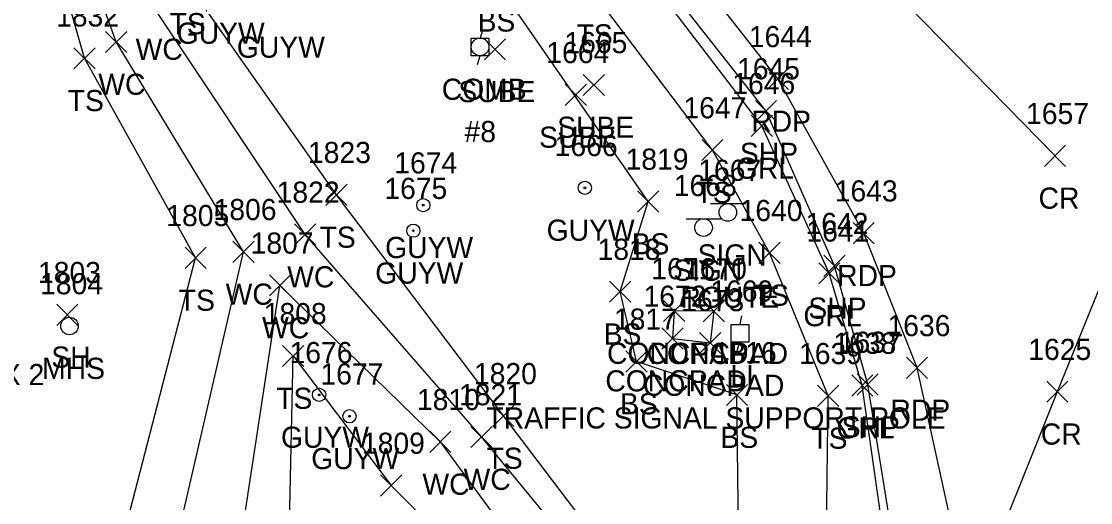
# Model space of a CAD drawing. Extents: x 1623612 to 1625808, y 621345 to 627748.
# Drawn here: x 1624593.7 to 1624694.8, y 626333.7 to 626379.2 of the extents above; entities that cross this region are included whole.
import ezdxf

# ---------------------------------------------------------------- set-up
doc = ezdxf.new("R2010")
doc.units = 0
for name, color, linetype in [('L_A', 7, 'Continuous'), ('L_I', 7, 'Continuous'), ('L_TIC', 7, 'Continuous'), ('LAWE', 7, 'Continuous'), ('LELB', 7, 'Continuous'), ('LS', 7, 'Continuous'), ('P_A', 7, 'Continuous'), ('P_I', 7, 'Continuous'), ('P_TIC', 7, 'Continuous'), ('PET', 7, 'Continuous'), ('PRC', 7, 'Continuous'), ('PSP', 7, 'Continuous'), ('R_A', 7, 'Continuous'), ('R_I', 7, 'Continuous'), ('R_TIC', 7, 'Continuous'), ('RGR', 7, 'Continuous'), ('S_A', 7, 'Continuous'), ('S_C', 7, 'Continuous'), ('S_I', 7, 'Continuous'), ('SSGN', 7, 'Continuous'), ('U_A', 7, 'Continuous'), ('U_C', 7, 'Continuous'), ('U_I', 7, 'Continuous'), ('U_TIC', 7, 'Continuous'), ('ULP', 7, 'Continuous'), ('UP', 7, 'Continuous'), ('UPGW', 7, 'Continuous'), ('USMH', 7, 'Continuous')]:
    doc.layers.add(name, color=color, linetype=linetype)

msp = doc.modelspace()

# ---------------------------------------------------------------- linework, layer by layer
at = {"layer": 'L_TIC'}
for points in [[(1624601.68, 626376.24), (1624603.68, 626378.24)], [(1624603.68, 626376.24), (1624601.68, 626378.24)], [(1624598.69, 626374.7), (1624600.69, 626376.7)], [(1624600.69, 626374.7), (1624598.69, 626376.7)], [(1624658.04, 626366.02), (1624660.04, 626368.02)], [(1624660.04, 626366.02), (1624658.04, 626368.02)], [(1624622.5, 626361.79), (1624624.5, 626363.79)], [(1624624.5, 626361.79), (1624622.5, 626363.79)], [(1624651.97, 626361.16), (1624653.97, 626363.16)], [(1624653.97, 626361.16), (1624651.97, 626363.16)], [(1624619.54, 626358.04), (1624621.54, 626360.04)], [(1624621.54, 626358.04), (1624619.54, 626360.04)], [(1624613.72, 626356.4), (1624615.72, 626358.4)], [(1624615.72, 626356.4), (1624613.72, 626358.4)], [(1624663.44, 626356.31), (1624665.44, 626358.31)], [(1624665.44, 626356.31), (1624663.44, 626358.31)], [(1624609.19, 626355.83), (1624611.19, 626357.83)], [(1624611.19, 626355.83), (1624609.19, 626357.83)], [(1624617.16, 626353.23), (1624619.16, 626355.23)], [(1624619.16, 626353.23), (1624617.16, 626355.23)], [(1624649.32, 626352.64), (1624651.32, 626354.64)], [(1624651.32, 626352.64), (1624649.32, 626354.64)], [(1624597.07, 626350.45), (1624599.07, 626352.45)], [(1624599.07, 626350.45), (1624597.07, 626352.45)], [(1624654.43, 626350.81), (1624656.43, 626352.81)], [(1624656.43, 626350.81), (1624654.43, 626352.81)], [(1624658.18, 626350.8), (1624660.18, 626352.8)], [(1624660.18, 626350.8), (1624658.18, 626352.8)], [(1624658.18, 626350.8), (1624660.18, 626352.8)], [(1624660.18, 626350.8), (1624658.18, 626352.8)], [(1624654.27, 626348.21), (1624656.27, 626350.21)], [(1624656.27, 626348.21), (1624654.27, 626350.21)], [(1624657.83, 626347.79), (1624659.83, 626349.79)], [(1624659.83, 626347.79), (1624657.83, 626349.79)], [(1624657.83, 626347.79), (1624659.83, 626349.79)], [(1624659.83, 626347.79), (1624657.83, 626349.79)], [(1624618.41, 626346.56), (1624620.41, 626348.56)], [(1624620.41, 626346.56), (1624618.41, 626348.56)], [(1624650.86, 626346.04), (1624652.86, 626348.04)], [(1624652.86, 626346.04), (1624650.86, 626348.04)], [(1624660.36, 626342.87), (1624662.36, 626344.87)], [(1624662.36, 626342.87), (1624660.36, 626344.87)], [(1624668.98, 626342.79), (1624670.98, 626344.79)], [(1624670.98, 626342.79), (1624668.98, 626344.79)], [(1624638.28, 626340.89), (1624640.28, 626342.89)], [(1624640.28, 626340.89), (1624638.28, 626342.89)], [(1624636.21, 626338.9), (1624638.21, 626340.9)], [(1624638.21, 626338.9), (1624636.21, 626340.9)], [(1624632.32, 626338.44), (1624634.32, 626340.44)], [(1624634.32, 626338.44), (1624632.32, 626340.44)], [(1624627.68, 626334.31), (1624629.68, 626336.31)], [(1624629.68, 626334.31), (1624627.68, 626336.31)]]:
    msp.add_lwpolyline(points, dxfattribs=at)
at = {"layer": 'LAWE'}
for points in [[(1624478.34, 625960.64), (1624502.51, 626006.49), (1624510.02, 626033.48), (1624538.01, 626022.07), (1624539, 626026.11), (1624515.37, 626039.01), (1624525.82, 626080.12), (1624541.49, 626122.12), (1624557.13, 626161.32), (1624574.3, 626199.4), (1624588.96, 626242.23), (1624604.56, 626282.04), (1624612.69, 626318.46), (1624618.16, 626354.23), (1624633.32, 626339.44), (1624651.01, 626315.35), (1624653.64, 626319.94), (1624637.21, 626339.9), (1624620.54, 626359.04), (1624606.22, 626380.55), (1624599.51, 626405.02), (1624601.1, 626417.17), (1624599.39, 626418.68), (1624597.72, 626417.92)], [(1624475.9, 625962), (1624495.4, 626010.74), (1624513.45, 626053.64), (1624523.83, 626080.72), (1624539.75, 626122.53), (1624554.03, 626163.77), (1624569.78, 626201.47), (1624586.16, 626244.06), (1624600.64, 626283.77), (1624605.98, 626319.56), (1624614.72, 626357.4), (1624602.68, 626377.24), (1624598.91, 626387.68), (1624595.49, 626400.19), (1624596.27, 626415.38)]]:
    msp.add_lwpolyline(points, dxfattribs=at)
at = {"layer": 'LELB'}
for points in [[(1624669.8, 626328.28), (1624669.98, 626343.79), (1624664.44, 626357.31), (1624659.04, 626367.02), (1624647.79, 626381.91), (1624630.66, 626395.22), (1624597.45, 626435.36), (1624575.8, 626460.21), (1624547.36, 626492.23), (1624525.96, 626513.7), (1624497.97, 626546.1), (1624463.72, 626581.44), (1624438.46, 626609.8)], [(1624405.5, 625728.14), (1624428.24, 625773.19), (1624451.7, 625813.41), (1624479.3, 625869.39), (1624496.23, 625906.08), (1624514.91, 625948.11), (1624536.21, 625990.48), (1624546.45, 626029.66), (1624561.04, 626063.21), (1624576.65, 626110.9), (1624590.48, 626147.32), (1624609.26, 626181.73), (1624628.06, 626219.01), (1624648.51, 626267.43), (1624661.85, 626303.08), (1624661.36, 626343.87), (1624651.86, 626347.04), (1624650.32, 626353.64), (1624652.97, 626362.16), (1624638.4, 626383.22), (1624618.17, 626397.94), (1624604.09, 626415.44)], [(1624658.53, 626316.55), (1624639.28, 626341.89), (1624623.5, 626362.79), (1624609.32, 626382.97), (1624602.55, 626406.54), (1624604.09, 626415.44)], [(1624375.32, 625803.31), (1624399.86, 625843.95), (1624436.39, 625893.65), (1624461.77, 625932.24), (1624474.24, 625964.36), (1624492.43, 626012.44), (1624506.84, 626058.35), (1624517.83, 626084.66), (1624533.25, 626127.2), (1624547.8, 626166.97), (1624564.84, 626204.52), (1624581.23, 626246.76), (1624598.57, 626285.31), (1624600.66, 626320.03), (1624610.19, 626356.83), (1624599.69, 626375.7), (1624596.69, 626386.19), (1624590.38, 626400.67)], [(1624618.75, 626317.35), (1624619.41, 626347.56), (1624628.68, 626335.31), (1624655.24, 626308.57)]]:
    msp.add_lwpolyline(points, dxfattribs=at)
at = {"layer": 'LS'}
for points in [[(1624659.18, 626351.8), (1624655.43, 626351.81), (1624655.27, 626349.21), (1624658.83, 626348.79)], [(1624659.18, 626351.8), (1624658.83, 626348.79)]]:
    msp.add_lwpolyline(points, dxfattribs=at)
at = {"layer": 'P_TIC'}
for points in [[(1624664.22, 626372.75), (1624666.22, 626374.75)], [(1624666.22, 626372.75), (1624664.22, 626374.75)], [(1624663.11, 626369.71), (1624665.11, 626371.71)], [(1624665.11, 626369.71), (1624663.11, 626371.71)], [(1624690.43, 626365.48), (1624692.43, 626367.48)], [(1624692.43, 626365.48), (1624690.43, 626367.48)], [(1624672.34, 626358.16), (1624674.34, 626360.16)], [(1624674.34, 626358.16), (1624672.34, 626360.16)], [(1624669.58, 626355.08), (1624671.58, 626357.08)], [(1624671.58, 626355.08), (1624669.58, 626357.08)], [(1624677.38, 626345.43), (1624679.38, 626347.43)], [(1624679.38, 626345.43), (1624677.38, 626347.43)], [(1624672.72, 626343.86), (1624674.72, 626345.86)], [(1624674.72, 626343.86), (1624672.72, 626345.86)], [(1624690.64, 626343.18), (1624692.64, 626345.18)], [(1624692.64, 626343.18), (1624690.64, 626345.18)]]:
    msp.add_lwpolyline(points, dxfattribs=at)
at = {"layer": 'PET'}
msp.add_lwpolyline([(1624682.54, 626327.48), (1624678.38, 626346.43), (1624673.34, 626359.16), (1624665.22, 626373.75), (1624654.29, 626387.74), (1624639.33, 626403.95), (1624606.52, 626439.12), (1624581.34, 626466.22), (1624553.07, 626496.91), (1624531.24, 626520.29), (1624503.05, 626550.6), (1624469.83, 626586.28), (1624436.59, 626622.29), (1624410.08, 626650.63), (1624383.72, 626678.98), (1624351.7, 626713.55), (1624321.29, 626745.92), (1624294.74, 626773.91), (1624265.91, 626805.6)], dxfattribs=at)
at = {"layer": 'PRC'}
for points in [[(1624691.43, 626366.48), (1624669.78, 626388.58), (1624647.94, 626412.24), (1624616.12, 626446.54), (1624589.59, 626475.6), (1624562.81, 626504.24), (1624540.57, 626528.3), (1624511.37, 626559.76), (1624478.76, 626595.67), (1624444.94, 626631.16), (1624418.89, 626658.65), (1624393.01, 626686.5), (1624360.17, 626722.63), (1624331.53, 626753.24), (1624304.47, 626782.71), (1624275.06, 626813.9), (1624246.4, 626843.61), (1624219.02, 626871.9), (1624198.62, 626894.75), (1624176.28, 626917.84)], [(1624715.94, 626400.49), (1624704.96, 626376.94), (1624691.64, 626344.18), (1624683.71, 626324.4)]]:
    msp.add_lwpolyline(points, dxfattribs=at)
at = {"layer": 'PSP'}
msp.add_lwpolyline([(1624676.55, 626327.48), (1624673.72, 626344.86), (1624670.58, 626356.08), (1624664.11, 626370.71), (1624652.39, 626385.59), (1624636.52, 626401.6), (1624603.46, 626436.72), (1624579, 626463.66), (1624550.01, 626494.21), (1624528.45, 626517.8), (1624500.38, 626548.3), (1624466.85, 626583.85), (1624433.64, 626619.4), (1624408.06, 626646.48), (1624380.64, 626676.32), (1624349.24, 626711.12), (1624317.97, 626743.62), (1624292.14, 626770.88), (1624262.1, 626803.32)], dxfattribs=at)
at = {"layer": 'R_TIC'}
for points in [[(1624662.71, 626368.31), (1624664.71, 626370.31)], [(1624664.71, 626368.31), (1624662.71, 626370.31)], [(1624669.09, 626354.37), (1624671.09, 626356.37)], [(1624671.09, 626354.37), (1624669.09, 626356.37)], [(1624672.21, 626343.76), (1624674.21, 626345.76)], [(1624674.21, 626343.76), (1624672.21, 626345.76)]]:
    msp.add_lwpolyline(points, dxfattribs=at)
at = {"layer": 'RGR'}
msp.add_lwpolyline([(1624571, 626060.25), (1624575.84, 626063.1), (1624580.53, 626069.08), (1624596.69, 626108.34), (1624613, 626148.3), (1624628.7, 626186.79), (1624643.47, 626223.61), (1624657.22, 626257.17), (1624667.59, 626283.36), (1624674.43, 626306.16), (1624675.65, 626327.64), (1624673.21, 626344.76), (1624670.09, 626355.37), (1624663.71, 626369.31), (1624651.72, 626385.04), (1624634.25, 626398.65)], dxfattribs=at)
at = {"layer": 'SSGN'}
for p, q in [((1624658.86, 626361.97), (1624662.19, 626361.97)), ((1624660.5, 626361.13), (1624660.5, 626361.13)), ((1624656.55, 626360.52), (1624659.88, 626360.52)), ((1624658.2, 626359.69), (1624658.2, 626359.69))]:
    msp.add_line(p, q, dxfattribs=at)
for centre in [(1624660.5, 626361.13), (1624658.2, 626359.69)]:
    msp.add_circle(centre, 0.833, dxfattribs=at)
at = {"layer": 'U_TIC'}
for points in [[(1624637.49, 626375.55), (1624639.49, 626377.55)], [(1624639.49, 626375.55), (1624637.49, 626377.55)], [(1624646.83, 626372.18), (1624648.83, 626374.18)], [(1624648.83, 626372.18), (1624646.83, 626374.18)], [(1624645.13, 626371.24), (1624647.13, 626373.24)], [(1624647.13, 626371.24), (1624645.13, 626373.24)]]:
    msp.add_lwpolyline(points, dxfattribs=at)
at = {"layer": 'ULP'}
for p, q in [((1624661.8, 626351.36), (1624661.63, 626350.53)), ((1624660.8, 626348.86), (1624660.8, 626350.53)), ((1624660.8, 626350.53), (1624662.47, 626350.53)), ((1624662.47, 626350.53), (1624662.47, 626348.86)), ((1624662.47, 626348.86), (1624660.8, 626348.86)), ((1624661.38, 626348.03), (1624661.63, 626348.86)), ((1624661.63, 626349.7), (1624661.63, 626349.7))]:
    msp.add_line(p, q, dxfattribs=at)
at = {"layer": 'UP'}
for p, q in [((1624637.33, 626378.43), (1624637.08, 626377.6)), ((1624636.24, 626375.93), (1624636.24, 626377.6)), ((1624636.24, 626377.6), (1624637.91, 626377.6)), ((1624637.91, 626377.6), (1624637.91, 626375.93)), ((1624637.08, 626376.77), (1624637.08, 626376.77)), ((1624637.91, 626375.93), (1624636.24, 626375.93)), ((1624636.83, 626375.1), (1624637.08, 626375.93))]:
    msp.add_line(p, q, dxfattribs=at)
msp.add_circle((1624637.08, 626376.77), 0.833, dxfattribs=at)
at = {"layer": 'UPGW'}
for centre, radius in [((1624646.98, 626363.45), 0.625), ((1624646.98, 626363.45), 0.0833), ((1624631.71, 626361.81), 0.625), ((1624631.71, 626361.81), 0.0833), ((1624630.77, 626359.4), 0.625), ((1624630.77, 626359.4), 0.0833), ((1624621.86, 626343.88), 0.625), ((1624621.86, 626343.88), 0.0833), ((1624624.73, 626341.86), 0.625), ((1624624.73, 626341.86), 0.0833)]:
    msp.add_circle(centre, radius, dxfattribs=at)
at = {"layer": 'USMH'}
for p, q in [((1624598.27, 626350.39), (1624598.27, 626350.39)), ((1624599.1, 626350.39), (1624599.1, 626350.39))]:
    msp.add_line(p, q, dxfattribs=at)
msp.add_circle((1624598.27, 626350.39), 0.833, dxfattribs=at)

# ---------------------------------------------------------------- texts
at = {"layer": 'L_A'}
for s, p in [('BS', (1624636.84, 626378.22)), ('TS', (1624607.73, 626377.97)), ('TS', (1624646.2, 626376.91)), ('WC', (1624604.52, 626375.55)), ('WC', (1624600.99, 626372.24)), ('TS', (1624598.1, 626370.7)), ('TS', (1624657.45, 626362.02)), ('TS', (1624621.91, 626357.79)), ('BS', (1624651.41, 626357.16)), ('WC', (1624618.85, 626354.04)), ('TS', (1624608.6, 626351.83)), ('WC', (1624613.03, 626352.4)), ('TS', (1624662.85, 626352.31)), ('WC', (1624616.47, 626349.23)), ('BS', (1624648.76, 626348.64)), ('CONCPAD', (1624649.08, 626346.81)), ('CONCPAD', (1624652.82, 626346.8)), ('CONCPAD', (1624652.82, 626346.8)), ('SH', (1624596.55, 626346.45)), ('CONCPAD', (1624648.92, 626344.21)), ('CONCPAD', (1624652.47, 626343.79)), ('CONCPAD', (1624652.47, 626343.79)), ('TS', (1624617.81, 626342.56)), ('BS', (1624650.3, 626342.04)), ('BS', (1624659.8, 626338.87)), ('TS', (1624668.39, 626338.79)), ('TS', (1624637.69, 626336.89)), ('WC', (1624635.52, 626334.9)), ('WC', (1624631.63, 626334.44))]:
    msp.add_text(s, height=2, dxfattribs=at).set_placement(p)
at = {"layer": 'L_I'}
for s, p in [('1832', (1624597, 626378.7)), ('1647', (1624656.3, 626370.02)), ('1823', (1624620.81, 626365.79)), ('1819', (1624650.83, 626365.16)), ('1822', (1624617.85, 626362.04)), ('1806', (1624611.89, 626360.4)), ('1640', (1624661.61, 626360.31)), ('1805', (1624607.42, 626359.83)), ('1807', (1624615.39, 626357.23)), ('1818', (1624648.19, 626356.64)), ('1803', (1624595.29, 626354.45)), ('1671', (1624653.26, 626354.81)), ('1670', (1624656.35, 626354.8)), ('1670', (1624656.35, 626354.8)), ('1672', (1624652.53, 626352.21)), ('1673', (1624656.09, 626351.79)), ('1673', (1624656.09, 626351.79)), ('1808', (1624616.63, 626350.56)), ('1817', (1624649.73, 626350.04)), ('1816', (1624659.17, 626346.87)), ('1639', (1624667.23, 626346.79)), ('1820', (1624636.5, 626344.89)), ('1821', (1624635.09, 626342.9)), ('1810', (1624631.11, 626342.44)), ('1809', (1624625.91, 626338.31))]:
    msp.add_text(s, height=2, dxfattribs=at).set_placement(p)
at = {"layer": 'P_A'}
for s, p in [('RDP', (1624662.71, 626368.75)), ('SHP', (1624661.64, 626365.71)), ('CR', (1624689.87, 626361.48)), ('RDP', (1624670.83, 626354.16)), ('SHP', (1624668.11, 626351.08)), ('RDP', (1624675.87, 626341.43)), ('SHP', (1624671.26, 626339.86)), ('CR', (1624690.08, 626339.18))]:
    msp.add_text(s, height=2, dxfattribs=at).set_placement(p)
at = {"layer": 'P_I'}
for s, p in [('1644', (1624662.48, 626376.75)), ('1645', (1624661.37, 626373.71)), ('1657', (1624688.69, 626369.48)), ('1643', (1624670.6, 626362.16)), ('1642', (1624667.84, 626359.08)), ('1636', (1624675.59, 626349.43)), ('1637', (1624670.98, 626347.86)), ('1625', (1624688.9, 626347.18))]:
    msp.add_text(s, height=2, dxfattribs=at).set_placement(p)
at = {"layer": 'R_A'}
for p in [(1624661.26, 626364.31), (1624667.64, 626350.37), (1624670.76, 626339.76)]:
    msp.add_text('GRL', height=2, dxfattribs=at).set_placement(p)
at = {"layer": 'R_I'}
for s, p in [('1646', (1624660.92, 626372.31)), ('1641', (1624667.92, 626358.37)), ('1638', (1624670.47, 626347.76))]:
    msp.add_text(s, height=2, dxfattribs=at).set_placement(p)
at = {"layer": 'S_A'}
for p in [(1624657.64, 626356.11), (1624655.33, 626354.67)]:
    msp.add_text('SIGN', height=2, dxfattribs=at).set_placement(p)
at = {"layer": 'S_C'}
msp.add_text('ROUTE', height=2, dxfattribs=at).set_placement((1624656.01, 626352.11))
at = {"layer": 'S_I'}
for s, p in [('1667', (1624657.7, 626364.11)), ('1668', (1624655.39, 626362.67))]:
    msp.add_text(s, height=2, dxfattribs=at).set_placement(p)
at = {"layer": 'U_A'}
for s, p in [('GUYW', (1624608.4, 626377.07)), ('GUYW', (1624614.09, 626375.75)), ('COMB', (1624633.46, 626371.77)), ('SUBE', (1624635.02, 626371.55)), ('SUBE', (1624644.37, 626368.18)), ('SUBE', (1624642.66, 626367.24)), ('GUYW', (1624643.37, 626358.45)), ('GUYW', (1624628.1, 626356.81)), ('GUYW', (1624627.17, 626354.4)), ('MHS', (1624595.68, 626345.39)), ('LI', (1624660.73, 626344.7)), ('GUYW', (1624618.26, 626338.88)), ('GUYW', (1624621.12, 626336.86))]:
    msp.add_text(s, height=2, dxfattribs=at).set_placement(p)
at = {"layer": 'U_C'}
for s, p in [('#8', (1624635.61, 626367.77)), ('TELEPHONE COMMUNICATIONS BOX 2', (1624545.36, 626344.8)), ('TRAFFIC SIGNAL SUPPORT POLE', (1624637.68, 626340.7))]:
    msp.add_text(s, height=2, dxfattribs=at).set_placement(p)
at = {"layer": 'U_I'}
for s, p in [('1665', (1624645.05, 626376.18)), ('1664', (1624643.34, 626375.24)), ('1666', (1624644.13, 626366.45)), ('1674', (1624628.97, 626364.81)), ('1675', (1624628.03, 626362.4)), ('1804', (1624595.49, 626353.39)), ('1669', (1624658.84, 626352.7)), ('1676', (1624619.07, 626346.88)), ('1677', (1624621.99, 626344.86))]:
    msp.add_text(s, height=2, dxfattribs=at).set_placement(p)

doc.saveas('drawing.dxf')
